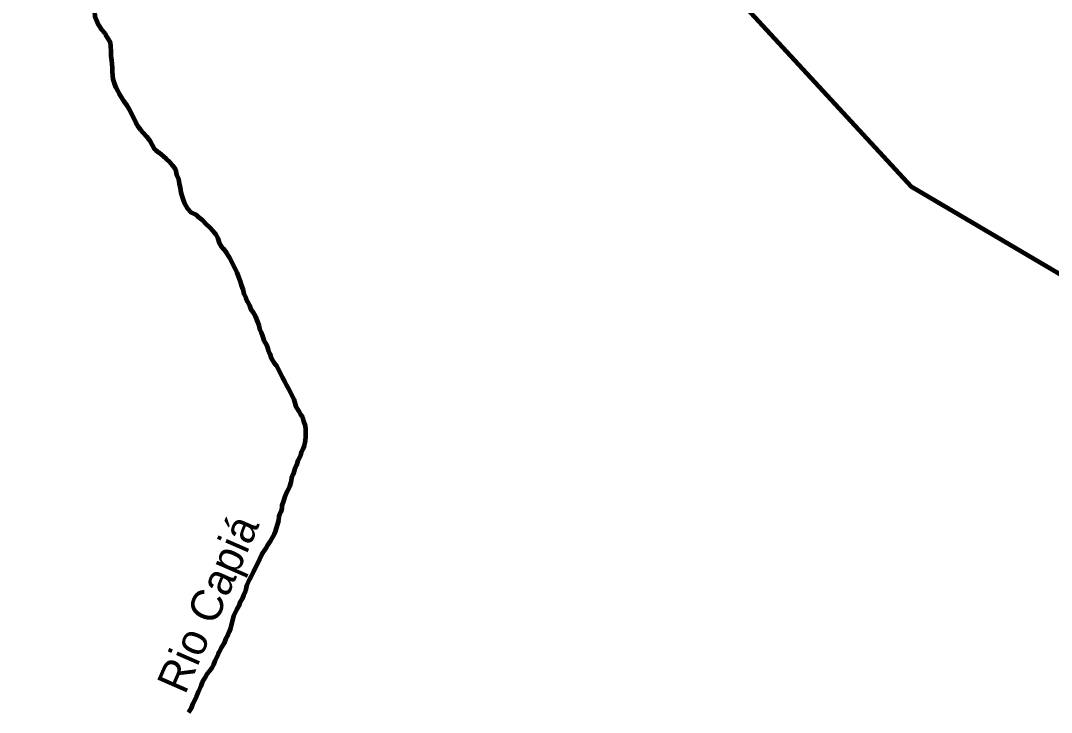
# Model space of a CAD drawing. Extents: x -1643653 to 4543381, y 1624270 to 13878484.
# Drawn here: x 644975 to 661208, y 8933613 to 8944499 of the extents above; entities that cross this region are included whole.
import ezdxf
from ezdxf.enums import TextEntityAlignment as Align

# ---------------------------------------------------------------- set-up
doc = ezdxf.new("R2010")
doc.units = 0
doc.header["$LTSCALE"] = 200
for name, color, linetype, lineweight in [('24', 7, 'Continuous', 25), ('26', 7, 'Continuous', 106), ('28', 7, 'Continuous', 53), ('60', 7, 'Continuous', 13), ('9', 7, 'Continuous', 90)]:
    doc.layers.add(name, color=color, linetype=linetype, lineweight=lineweight)
doc.layers.add('49', color=7, linetype='Continuous')

msp = doc.modelspace()

# ---------------------------------------------------------------- linework, layer by layer
at = {"layer": '24', "lineweight": 53}
for points in [[(645925.1, 8945520.2), (645980.3, 8945480.9), (646030.3, 8945430.9), (646080.3, 8945396.3), (646111.1, 8945361.7), (646137.1, 8945322.6), (646171.8, 8945257.3), (646176.4, 8945189.8), (646181.1, 8945124.7), (646180.8, 8945062.1), (646173.1, 8945007.1), (646162.8, 8944947.2), (646155, 8944897.2), (646149.8, 8944847.1), (646141.9, 8944777.1), (646139.2, 8944722.1), (646138.8, 8944644.6), (646145.9, 8944567), (646168.2, 8944506.8), (646200.3, 8944434.1), (646247.5, 8944358.8), (646299.8, 8944301), (646309, 8944284.7)], [(646309, 8944284.7), (646346.9, 8944218.2), (646384.2, 8944160.4), (646391.3, 8944097.8), (646395.9, 8944012.8), (646398.1, 8943942.7), (646405.3, 8943872.6), (646412.5, 8943820), (646414.7, 8943755), (646419.5, 8943702.4), (646424.2, 8943637.3), (646428.9, 8943577.3), (646446.1, 8943512.1), (646475.8, 8943444.4), (646508, 8943389.2), (646527.8, 8943344.1), (646562.6, 8943288.9), (646604.8, 8943221.1), (646647, 8943160.8), (646684.3, 8943105.6), (646721.5, 8943027.8), (646756.1, 8942957.6), (646790.8, 8942889.9), (646825.6, 8942829.7), (646865.4, 8942779.4), (646902.7, 8942731.7), (646957.4, 8942676.4), (647012.1, 8942606), (647046.8, 8942538.3), (647076.6, 8942480.6), (647102.9, 8942459), (647151.9, 8942424.7), (647151.9, 8942424.7), (647259.8, 8942331.6), (647323.5, 8942272.8), (647367.7, 8942218.9), (647416.7, 8942155.2), (647431.4, 8942071.9), (647460.8, 8942003.3), (647470.7, 8941934.7), (647485.4, 8941866.1), (647498.6, 8941792.9), (647513.3, 8941742.8), (647538, 8941665.1), (647557.8, 8941619.9), (647597.5, 8941547.2), (647657.2, 8941484.3), (647722.1, 8941454), (647762, 8941421.2), (647826.8, 8941368.3), (647896.5, 8941297.9), (647948.8, 8941250.1), (648011, 8941182.2), (648043.4, 8941142.1), (648083.1, 8941071.8), (648100.2, 8941001.6), (648132.5, 8940948.9), (648170.9, 8940907.9), (648214.2, 8940849.2), (648257.5, 8940775), (648294.6, 8940700.8), (648325.5, 8940642.1), (648353.4, 8940586.5), (648378.1, 8940533.9), (648399.8, 8940478.3), (648430.7, 8940394.8), (648446.2, 8940342.3), (648474, 8940274.3), (648489.2, 8940201.5), (648521.4, 8940133.8), (648546.1, 8940073.6), (648581.1, 8940014.6), (648600.6, 8939953.5), (648636.7, 8939906.2), (648667.3, 8939850.6), (648703.5, 8939758.8), (648725.8, 8939700.4), (648739.7, 8939647.6), (648762, 8939592), (648787, 8939533.6), (648806.5, 8939466.9), (648845.4, 8939394.6), (648873.2, 8939316.7), (648898.3, 8939255.5), (648922.2, 8939185.9), (648969.4, 8939115.6), (649001.7, 8939077.9), (649063.7, 8938952.5), (649095.9, 8938889.7), (649130.6, 8938824.5), (649157.8, 8938769.3), (649200, 8938691.5), (649276.8, 8938536), (649291.6, 8938483.4), (649308.8, 8938428.2), (649356, 8938355.4), (649380.8, 8938302.8), (649415.6, 8938260), (649432.8, 8938197.4), (649457.5, 8938124.7), (649458.7, 8938112.5)], [(649458.7, 8938112.5), (649462.3, 8938074.6), (649461.7, 8937947), (649458.9, 8937884.5), (649441, 8937814.5), (649418.2, 8937754.6), (649393, 8937709.7), (649382.7, 8937654.7), (649342.3, 8937574.8), (649321.9, 8937502.4), (649286.6, 8937427.5), (649266.2, 8937362.5), (649243.4, 8937297.6), (649233.1, 8937237.6), (649207.7, 8937165.2), (649172.4, 8937090.3), (649131.8, 8936990.4), (649111.5, 8936927.9), (649091.2, 8936868), (649088.5, 8936820.5), (649070.7, 8936768), (649042.9, 8936693.1), (649035.1, 8936630.6), (649014.7, 8936565.6), (648986.8, 8936473.2), (648966.5, 8936418.2), (648928.6, 8936343.4), (648898.4, 8936298.5), (648858, 8936233.6), (648830.3, 8936188.7), (648774.8, 8936103.9), (648736.9, 8936024.1), (648704.1, 8935954.2), (648671.2, 8935886.8), (648635.9, 8935819.4), (648605.6, 8935757), (648582.3, 8935707.9)], [(648582.3, 8935707.9), (648534.8, 8935604.7), (648516.9, 8935524.8), (648484, 8935454.9), (648466.2, 8935397.4), (648428.4, 8935342.6), (648410.7, 8935290.1), (648377.9, 8935235.2), (648347.6, 8935175.3), (648327.3, 8935125.4), (648299.3, 8935022.9), (648281.4, 8934937.9), (648258.6, 8934878), (648238.3, 8934825.6), (648200.5, 8934765.7), (648180.2, 8934700.8), (648132.3, 8934628.4), (648104.5, 8934563.5), (648085.8, 8934528.5)], [(648085.8, 8934528.5), (648033.8, 8934426.2), (648013.5, 8934366.3), (647988.2, 8934313.9), (647947.9, 8934264), (647910.1, 8934214.2), (647874.8, 8934156.8), (647837, 8934086.9), (647811.7, 8934027), (647776.2, 8933942.1), (647745.8, 8933864.7), (647682.7, 8933739.9), (647662.4, 8933680), (647619.5, 8933610.1)]]:
    msp.add_lwpolyline(points, dxfattribs=at)
at = {"layer": '26'}
msp.add_lwpolyline([(645793.1, 8949290.9), (653495.4, 8947850), (659002.1, 8941889), (662654, 8939737.7), (668185.2, 8933928.8)], dxfattribs=at)
at = {"layer": '28'}
msp.add_lwpolyline([(645793.1, 8949290.9), (653495.4, 8947850), (659002.1, 8941889), (661559, 8940382.7), (661583.1, 8940454)], dxfattribs=at)
at = {"layer": '60', "lineweight": 25}
msp.add_spline([(814781, 9009175.5), (814787.2, 9009173.4), (814796.9, 9009173.4), (814799.4, 9009172.4), (814805.1, 9009174.5), (814805.6, 9009176.5), (814811.7, 9009179.5), (814811.7, 9009179.5), (814801.5, 9009181), (814790.7, 9009181.5), (814784.1, 9009183.1), (814777.4, 9009185.1), (814778.4, 9009175.5)], degree=3, dxfattribs=at)
at = {"layer": '9'}
for points in [[(645793.1, 8949290.9), (653495.4, 8947850), (659002.1, 8941889), (662654, 8939737.7), (668185.2, 8933928.8)], [(645925.1, 8945520.2), (645980.3, 8945480.9), (646030.3, 8945430.9), (646080.3, 8945396.3), (646111.1, 8945361.7), (646137.1, 8945322.6), (646171.8, 8945257.3), (646176.4, 8945189.8), (646181.1, 8945124.7), (646180.8, 8945062.1), (646173.1, 8945007.1), (646162.8, 8944947.2), (646155, 8944897.2), (646149.8, 8944847.1), (646141.9, 8944777.1), (646139.2, 8944722.1), (646138.8, 8944644.6), (646145.9, 8944567), (646168.2, 8944506.8), (646200.3, 8944434.1), (646247.5, 8944358.8), (646299.8, 8944301), (646309, 8944284.7)], [(646309, 8944284.7), (646346.9, 8944218.2), (646384.2, 8944160.4), (646391.3, 8944097.8), (646395.9, 8944012.8), (646398.1, 8943942.7), (646405.3, 8943872.6), (646412.5, 8943820), (646414.7, 8943755), (646419.5, 8943702.4), (646424.2, 8943637.3), (646428.9, 8943577.3), (646446.1, 8943512.1), (646475.8, 8943444.4), (646508, 8943389.2), (646527.8, 8943344.1), (646562.6, 8943288.9), (646604.8, 8943221.1), (646647, 8943160.8), (646684.3, 8943105.6), (646721.5, 8943027.8), (646756.1, 8942957.6), (646790.8, 8942889.9), (646825.6, 8942829.7), (646865.4, 8942779.4), (646902.7, 8942731.7), (646957.4, 8942676.4), (647012.1, 8942606), (647046.8, 8942538.3), (647076.6, 8942480.6), (647102.9, 8942459), (647151.9, 8942424.7), (647151.9, 8942424.7), (647259.8, 8942331.6), (647323.5, 8942272.8), (647367.7, 8942218.9), (647416.7, 8942155.2), (647431.4, 8942071.9), (647460.8, 8942003.3), (647470.7, 8941934.7), (647485.4, 8941866.1), (647498.6, 8941792.9), (647513.3, 8941742.8), (647538, 8941665.1), (647557.8, 8941619.9), (647597.5, 8941547.2), (647657.2, 8941484.3), (647722.1, 8941454), (647762, 8941421.2), (647826.8, 8941368.3), (647896.5, 8941297.9), (647948.8, 8941250.1), (648011, 8941182.2), (648043.4, 8941142.1), (648083.1, 8941071.8), (648100.2, 8941001.6), (648132.5, 8940948.9), (648170.9, 8940907.9), (648214.2, 8940849.2), (648257.5, 8940775), (648294.6, 8940700.8), (648325.5, 8940642.1), (648353.4, 8940586.5), (648378.1, 8940533.9), (648399.8, 8940478.3), (648430.7, 8940394.8), (648446.2, 8940342.3), (648474, 8940274.3), (648489.2, 8940201.5), (648521.4, 8940133.8), (648546.1, 8940073.6), (648581.1, 8940014.6), (648600.6, 8939953.5), (648636.7, 8939906.2), (648667.3, 8939850.6), (648703.5, 8939758.8), (648725.8, 8939700.4), (648739.7, 8939647.6), (648762, 8939592), (648787, 8939533.6), (648806.5, 8939466.9), (648845.4, 8939394.6), (648873.2, 8939316.7), (648898.3, 8939255.5), (648922.2, 8939185.9), (648969.4, 8939115.6), (649001.7, 8939077.9), (649063.7, 8938952.5), (649095.9, 8938889.7), (649130.6, 8938824.5), (649157.8, 8938769.3), (649200, 8938691.5), (649276.8, 8938536), (649291.6, 8938483.4), (649308.8, 8938428.2), (649356, 8938355.4), (649380.8, 8938302.8), (649415.6, 8938260), (649432.8, 8938197.4), (649457.5, 8938124.7), (649458.7, 8938112.5)], [(649458.7, 8938112.5), (649462.3, 8938074.6), (649461.7, 8937947), (649458.9, 8937884.5), (649441, 8937814.5), (649418.2, 8937754.6), (649393, 8937709.7), (649382.7, 8937654.7), (649342.3, 8937574.8), (649321.9, 8937502.4), (649286.6, 8937427.5), (649266.2, 8937362.5), (649243.4, 8937297.6), (649233.1, 8937237.6), (649207.7, 8937165.2), (649172.4, 8937090.3), (649131.8, 8936990.4), (649111.5, 8936927.9), (649091.2, 8936868), (649088.5, 8936820.5), (649070.7, 8936768), (649042.9, 8936693.1), (649035.1, 8936630.6), (649014.7, 8936565.6), (648986.8, 8936473.2), (648966.5, 8936418.2), (648928.6, 8936343.4), (648898.4, 8936298.5), (648858, 8936233.6), (648830.3, 8936188.7), (648774.8, 8936103.9), (648736.9, 8936024.1), (648704.1, 8935954.2), (648671.2, 8935886.8), (648635.9, 8935819.4), (648605.6, 8935757), (648582.3, 8935707.9)], [(648582.3, 8935707.9), (648534.8, 8935604.7), (648516.9, 8935524.8), (648484, 8935454.9), (648466.2, 8935397.4), (648428.4, 8935342.6), (648410.7, 8935290.1), (648377.9, 8935235.2), (648347.6, 8935175.3), (648327.3, 8935125.4), (648299.3, 8935022.9), (648281.4, 8934937.9), (648258.6, 8934878), (648238.3, 8934825.6), (648200.5, 8934765.7), (648180.2, 8934700.8), (648132.3, 8934628.4), (648104.5, 8934563.5), (648085.8, 8934528.5)], [(648085.8, 8934528.5), (648033.8, 8934426.2), (648013.5, 8934366.3), (647988.2, 8934313.9), (647947.9, 8934264), (647910.1, 8934214.2), (647874.8, 8934156.8), (647837, 8934086.9), (647811.7, 8934027), (647776.2, 8933942.1), (647745.8, 8933864.7), (647682.7, 8933739.9), (647662.4, 8933680), (647619.5, 8933610.1)]]:
    msp.add_lwpolyline(points, dxfattribs=at)
msp.add_spline([(637260.6, 8972975.8), (641524.5, 8971056.2), (652526.1, 8965412.7), (653164.3, 8965062.8), (670790.5, 8953770.1), (686194, 8943929.9), (696283.3, 8937647.1)], degree=3, dxfattribs=at)

# ---------------------------------------------------------------- texts
at = {"layer": '49'}
msp.add_text('Rio Capiá', height=500, rotation=66.381, dxfattribs=at).set_placement((648152.9, 8935223.9), align=Align.CENTER)

doc.saveas('drawing.dxf')
